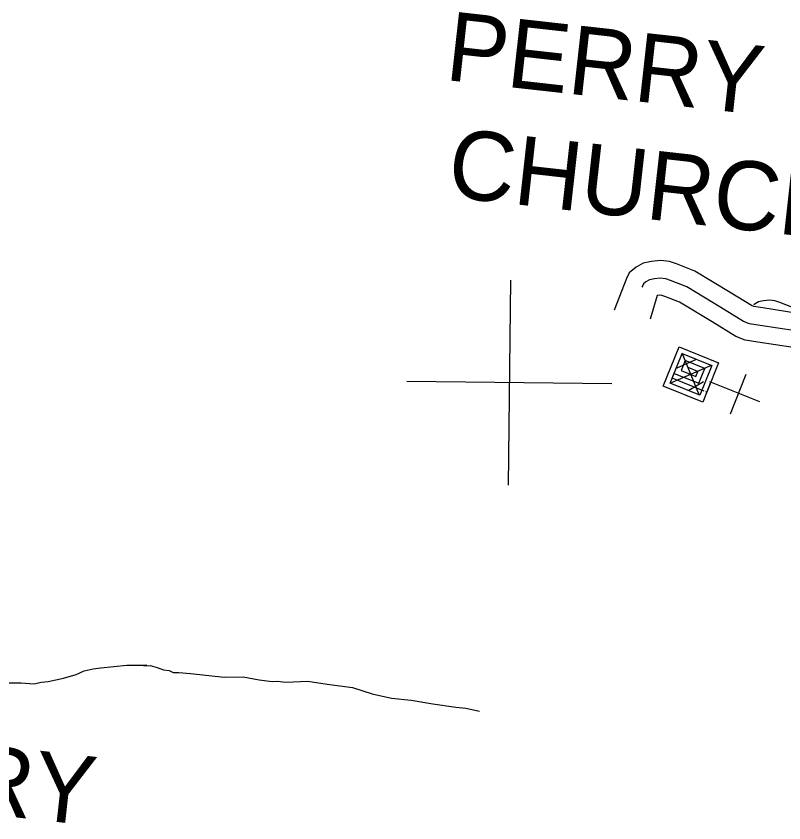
# Model space of a CAD drawing. Extents: x 1551132 to 1791609, y 378168 to 563823.
# Drawn here: x 1643400 to 1647521, y 424098 to 428427 of the extents above; entities that cross this region are included whole.
import ezdxf

# ---------------------------------------------------------------- set-up
doc = ezdxf.new("R2010")
doc.units = 0
for name, color, linetype in [('DESIGN - ROW - Right-of-Way and Easement Labels', 7, 'Continuous'), ('DESIGN - TRANSPORTATION - Text', 7, 'Continuous'), ('DESIGN - UTILITIES - Cable (Underground) with Text', 7, 'Continuous'), ('SURVEY - DRAINAGE - Bridge Hydraulic Data - Points - Locators', 7, 'Continuous'), ('SURVEY - PROPERTY - Owners', 7, 'Continuous')]:
    doc.layers.add(name, color=color, linetype=linetype)

msp = doc.modelspace()

# ---------------------------------------------------------------- linework, layer by layer
at = {"layer": 'DESIGN - TRANSPORTATION - Text'}
msp.add_lwpolyline([(1643331.115, 424850.253), (1643427.104, 424849.57), (1643495.069, 424845.086), (1643535.118, 424852.811), (1643571.143, 424856.561), (1643653.257, 424874.012), (1643721.381, 424893.563), (1643765.513, 424913.28), (1643813.587, 424924.955), (1643853.619, 424930.68), (1643993.699, 424943.714), (1644101.705, 424944.947), (1644085.681, 424941.056), (1644119.688, 424942.822), (1644157.621, 424932.539), (1644191.545, 424920.272), (1644221.511, 424916.055), (1644243.444, 424905.88), (1644273.443, 424905.671), (1644335.4, 424899.221), (1644517.262, 424879.904), (1644619.268, 424881.179), (1644705.174, 424866.554), (1644775.098, 424856.037), (1644801.114, 424857.854), (1644847.079, 424853.529), (1644965.11, 424858.696), (1645068.999, 424841.937), (1645136.939, 424833.445), (1645204.879, 424824.945), (1645310.652, 424790.144), (1645414.499, 424767.368), (1645520.422, 424756.602), (1645636.294, 424737.751), (1645760.166, 424718.842), (1645814.14, 424714.451), (1645888.03, 424697.9)], dxfattribs=at)
at = {"layer": 'DESIGN - UTILITIES - Cable (Underground) with Text'}
msp.add_line((1647233.811, 426293.875), (1647319.174, 426505.355), dxfattribs=at)
for points in [[(1647132.87, 426459.929), (1647128.07, 426461.687), (1647085.447, 426356.013), (1646873.909, 426441.793), (1646959.605, 426653.031), (1647171.043, 426567.485), (1647106.813, 426409.021), (1647102.979, 426410.479)], [(1647093.571, 426414.437), (1646921.716, 426483.976), (1646975.163, 426615.99), (1647133.986, 426551.777), (1647069.83, 426393.271), (1646911.016, 426457.184), (1646932.457, 426510.25), (1647064.788, 426456.753), (1647096.487, 426536.085), (1646991.072, 426578.833), (1646969.723, 426525.967), (1647048.78, 426493.994), (1647059.471, 426520.351), (1647006.822, 426541.659)], [(1647069.022, 426391.471), (1646975.246, 426618.448)], [(1647049.945, 426584.908), (1646946.148, 426538.791)], [(1647130.769, 426551.91), (1646913.4, 426457.768)], [(1647089.479, 426465.111), (1647010.748, 426418.311)], [(1647392.949, 426357.234), (1647122.77, 426464.045)]]:
    msp.add_lwpolyline(points, dxfattribs=at)
at = {"layer": 'SURVEY - DRAINAGE - Bridge Hydraulic Data - Points - Locators'}
for p, q in [((1646053.702, 427009.494), (1646041.06, 425909.54)), ((1646597.331, 426453.197), (1645497.432, 426465.838))]:
    msp.add_line(p, q, dxfattribs=at)
at = {"layer": 'SURVEY - PROPERTY - Owners'}
for points in [[(1648246.609, 426757.839), (1648085.946, 426776.881), (1647596.491, 426831.449), (1647408.537, 426861.041), (1647360.622, 426868.125), (1647346.797, 426873.466), (1647232.508, 426944.427), (1647042.504, 427058.621), (1646944.848, 427097.505), (1646907.682, 427109.506), (1646858.475, 427116.273), (1646810.885, 427111.181), (1646765.427, 427100.922), (1646727.445, 427080.255), (1646690.454, 427049.096), (1646676.529, 427019.92), (1646610.073, 426849.599)], [(1648235.518, 426664.203), (1648075.171, 426683.204), (1647583.933, 426737.971), (1647394.312, 426767.822), (1647336.422, 426776.381), (1647304.556, 426788.706), (1647183.351, 426863.958), (1647000.505, 426973.852), (1646912.891, 427008.736), (1646886.616, 427017.22), (1646857.042, 427021.287), (1646826.326, 427018.003), (1646798.977, 427011.828), (1646780.885, 427001.986), (1646766.777, 426990.103), (1646763.111, 426982.419), (1646759.519, 426973.219)], [(1648224.843, 426574.126), (1648064.813, 426593.084), (1647571.85, 426648.044), (1647380.629, 426678.145), (1647313.139, 426688.128), (1647263.924, 426707.162), (1647136.069, 426786.547), (1646960.098, 426892.3), (1646882.15, 426923.343), (1646866.35, 426928.443), (1646855.667, 426929.909), (1646841.184, 426928.368), (1646803.226, 426801.156)], [(1649868.013, 426440.398), (1649671.667, 426453.323), (1649529.804, 426460.69), (1649194.362, 426501.949), (1648661.224, 426565.117), (1648169.986, 426619.885), (1647980.365, 426649.736), (1647922.475, 426658.294), (1647890.609, 426670.62), (1647769.404, 426745.872), (1647586.558, 426855.766), (1647498.943, 426890.65), (1647472.669, 426899.134), (1647443.095, 426903.201), (1647412.379, 426899.917), (1647385.029, 426893.742), (1647366.938, 426883.9), (1647360.105, 426878.142)]]:
    msp.add_lwpolyline(points, dxfattribs=at)

# ---------------------------------------------------------------- texts
at = {"layer": 'DESIGN - ROW - Right-of-Way and Easement Labels'}
for s, rotation, p in [('PERRY', 353.638478, (1645696.201, 428085.132)), ('CHURCH RD.', 353.638478, (1645706.376, 427458.883)), ('PERRY', 353.638225, (1642110.368, 424271.495))]:
    msp.add_text(s, height=369.9915, rotation=rotation, dxfattribs=at).set_placement(p)

doc.saveas('drawing.dxf')
